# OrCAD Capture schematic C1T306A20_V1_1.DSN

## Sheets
1 PwrStr-3V3-S3
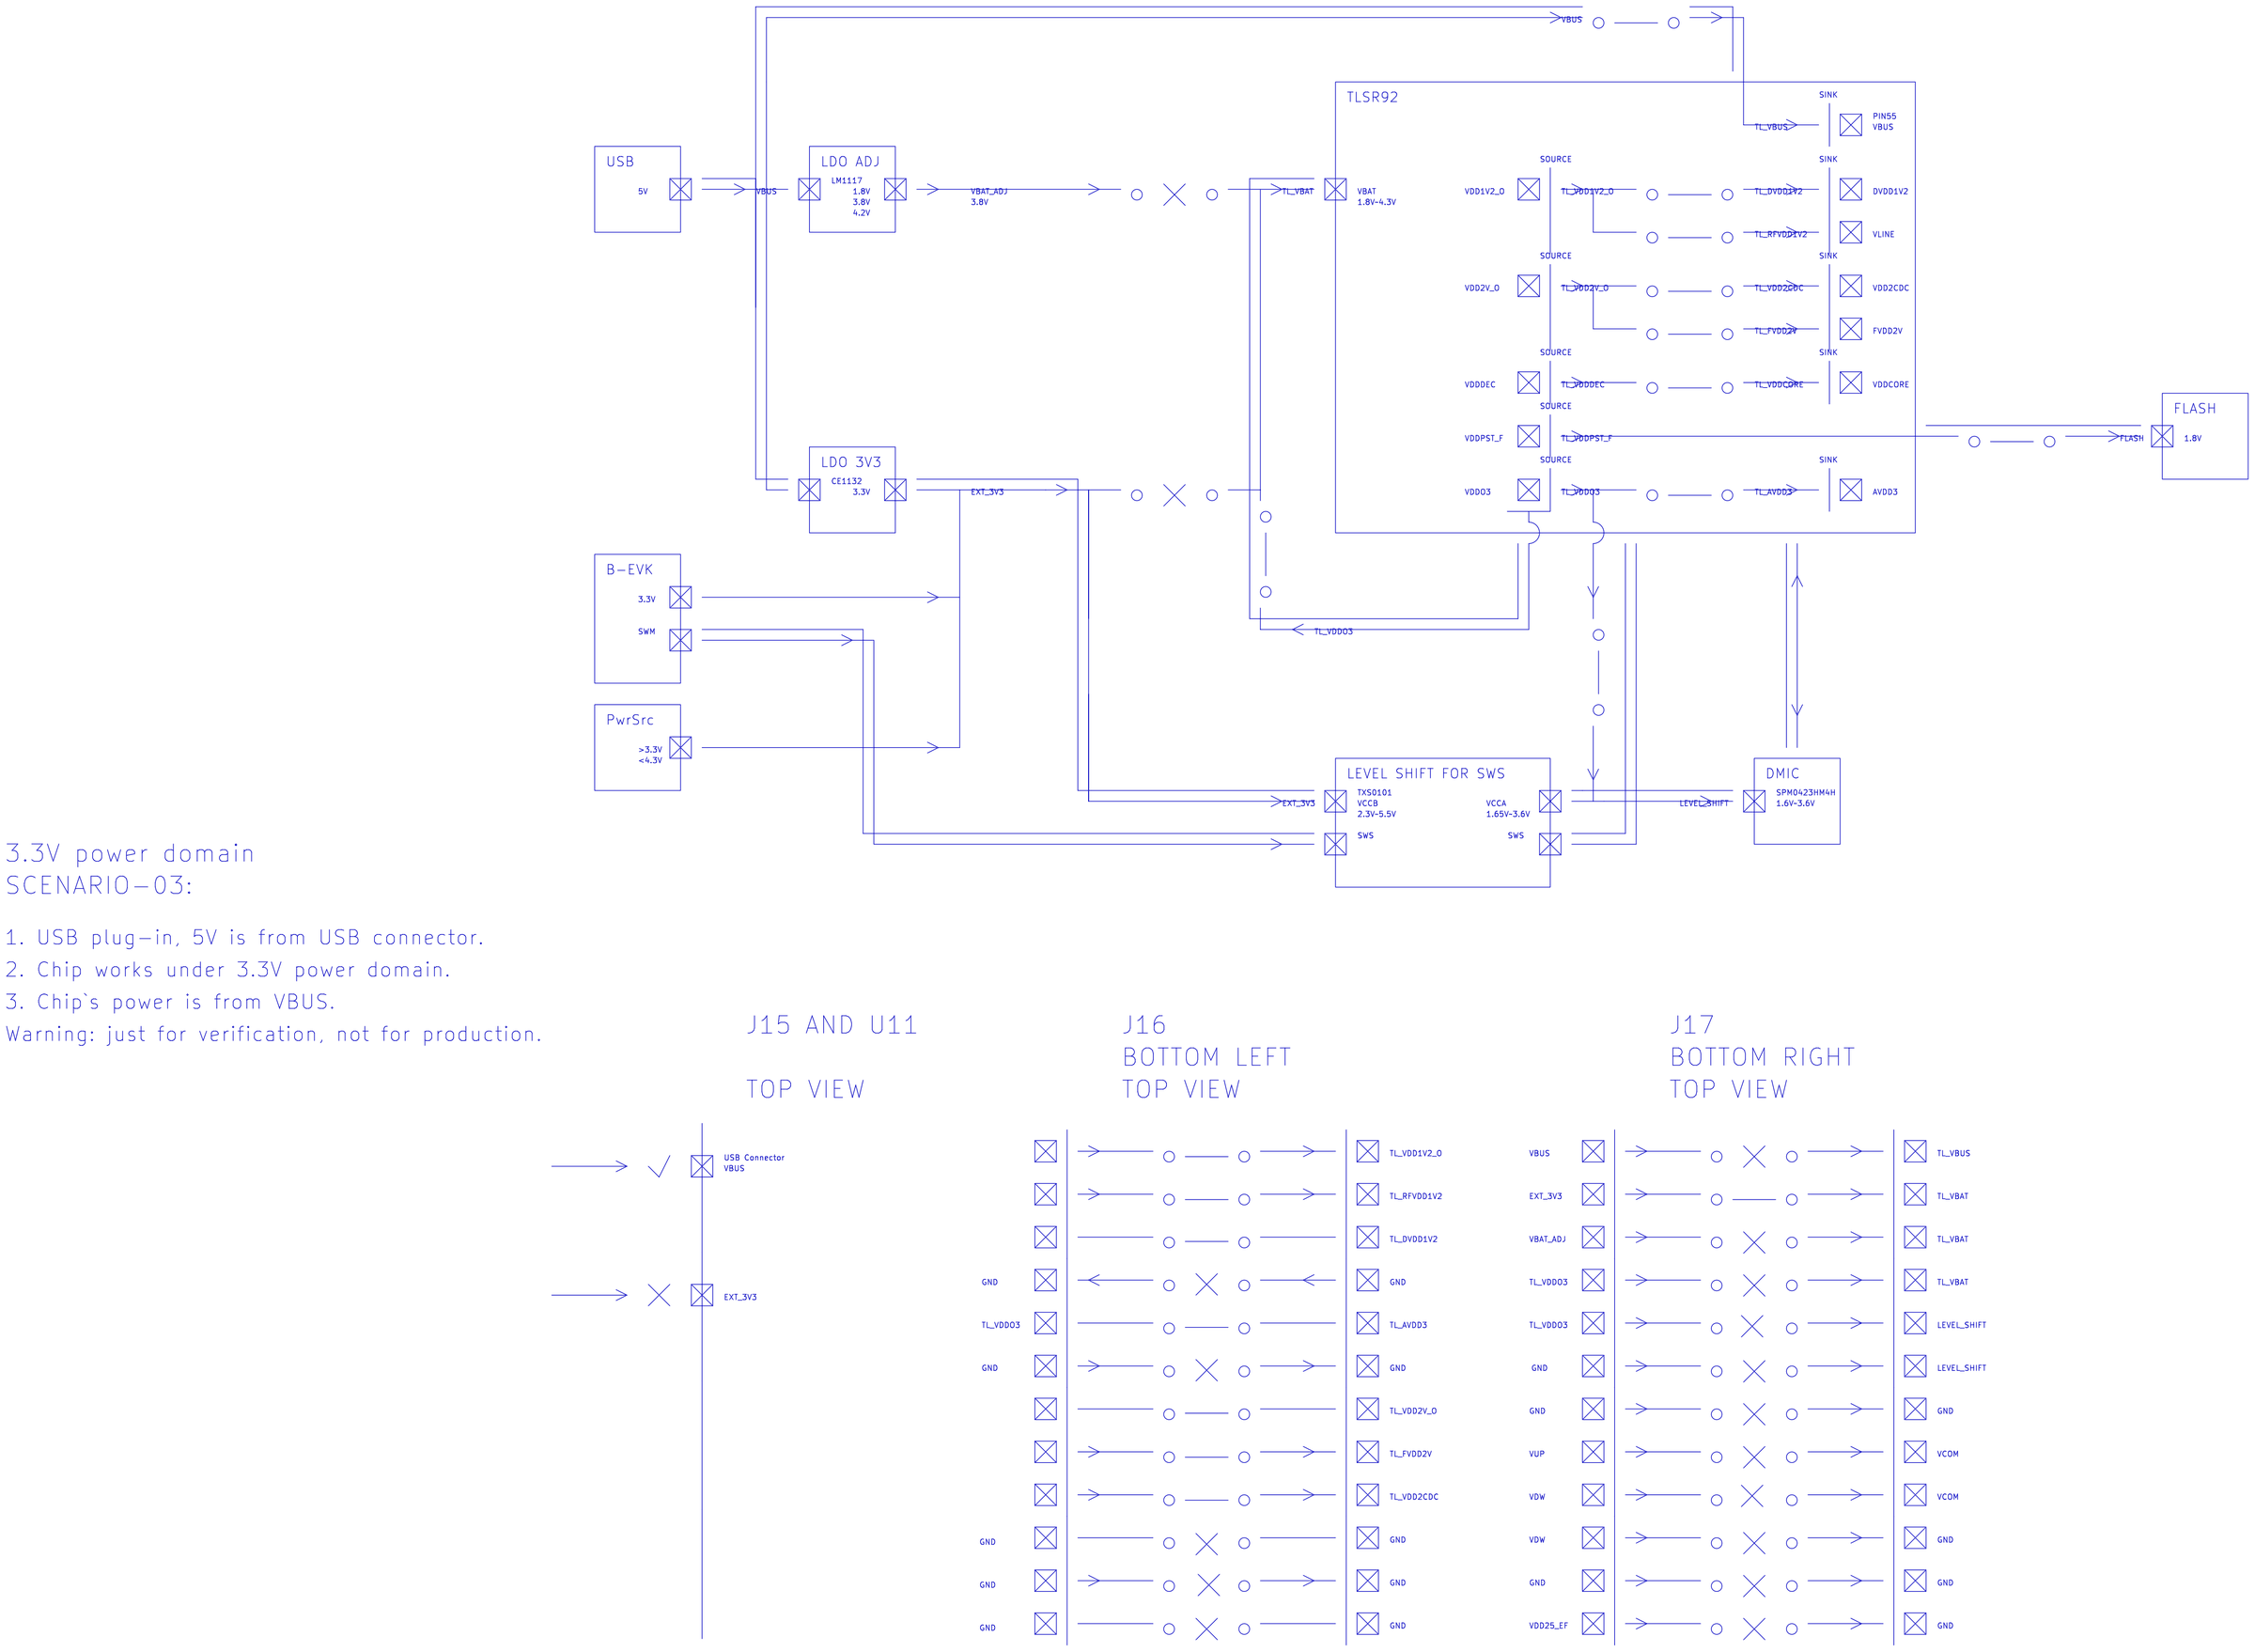
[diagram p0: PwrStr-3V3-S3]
2 PwrStr-3V3-S2
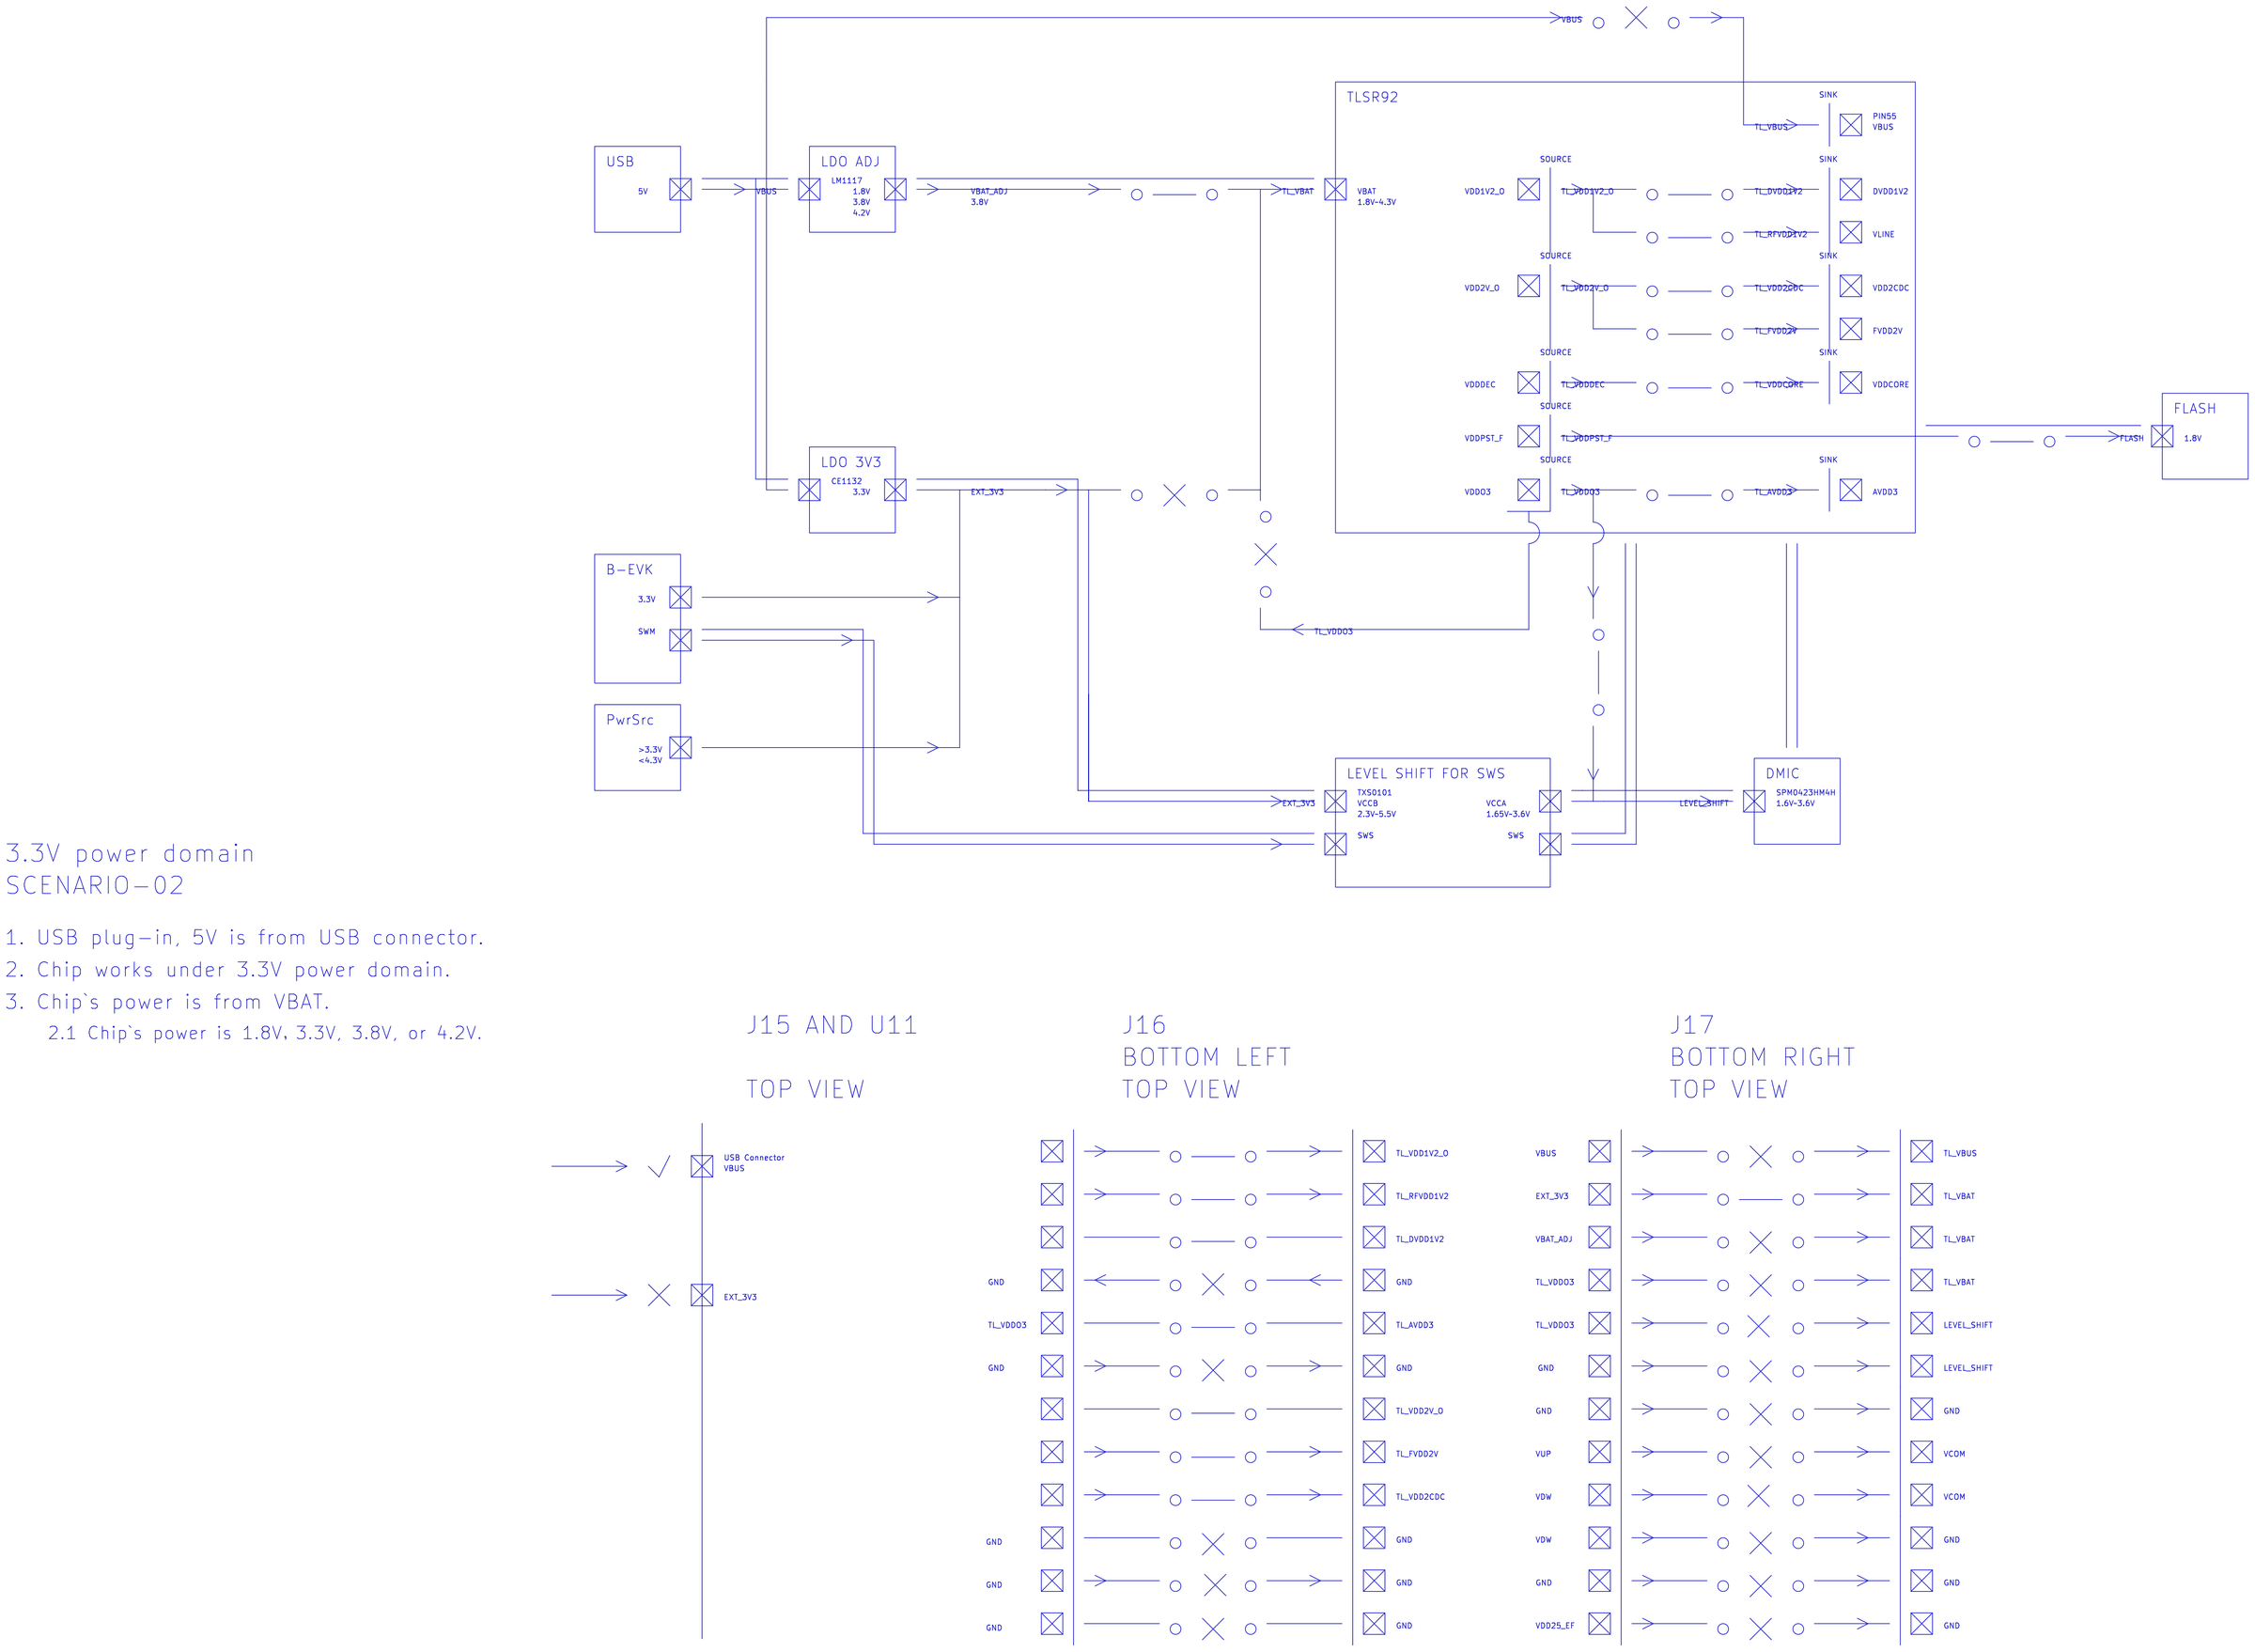
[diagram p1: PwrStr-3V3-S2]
3 PwrStr-3V3-S1
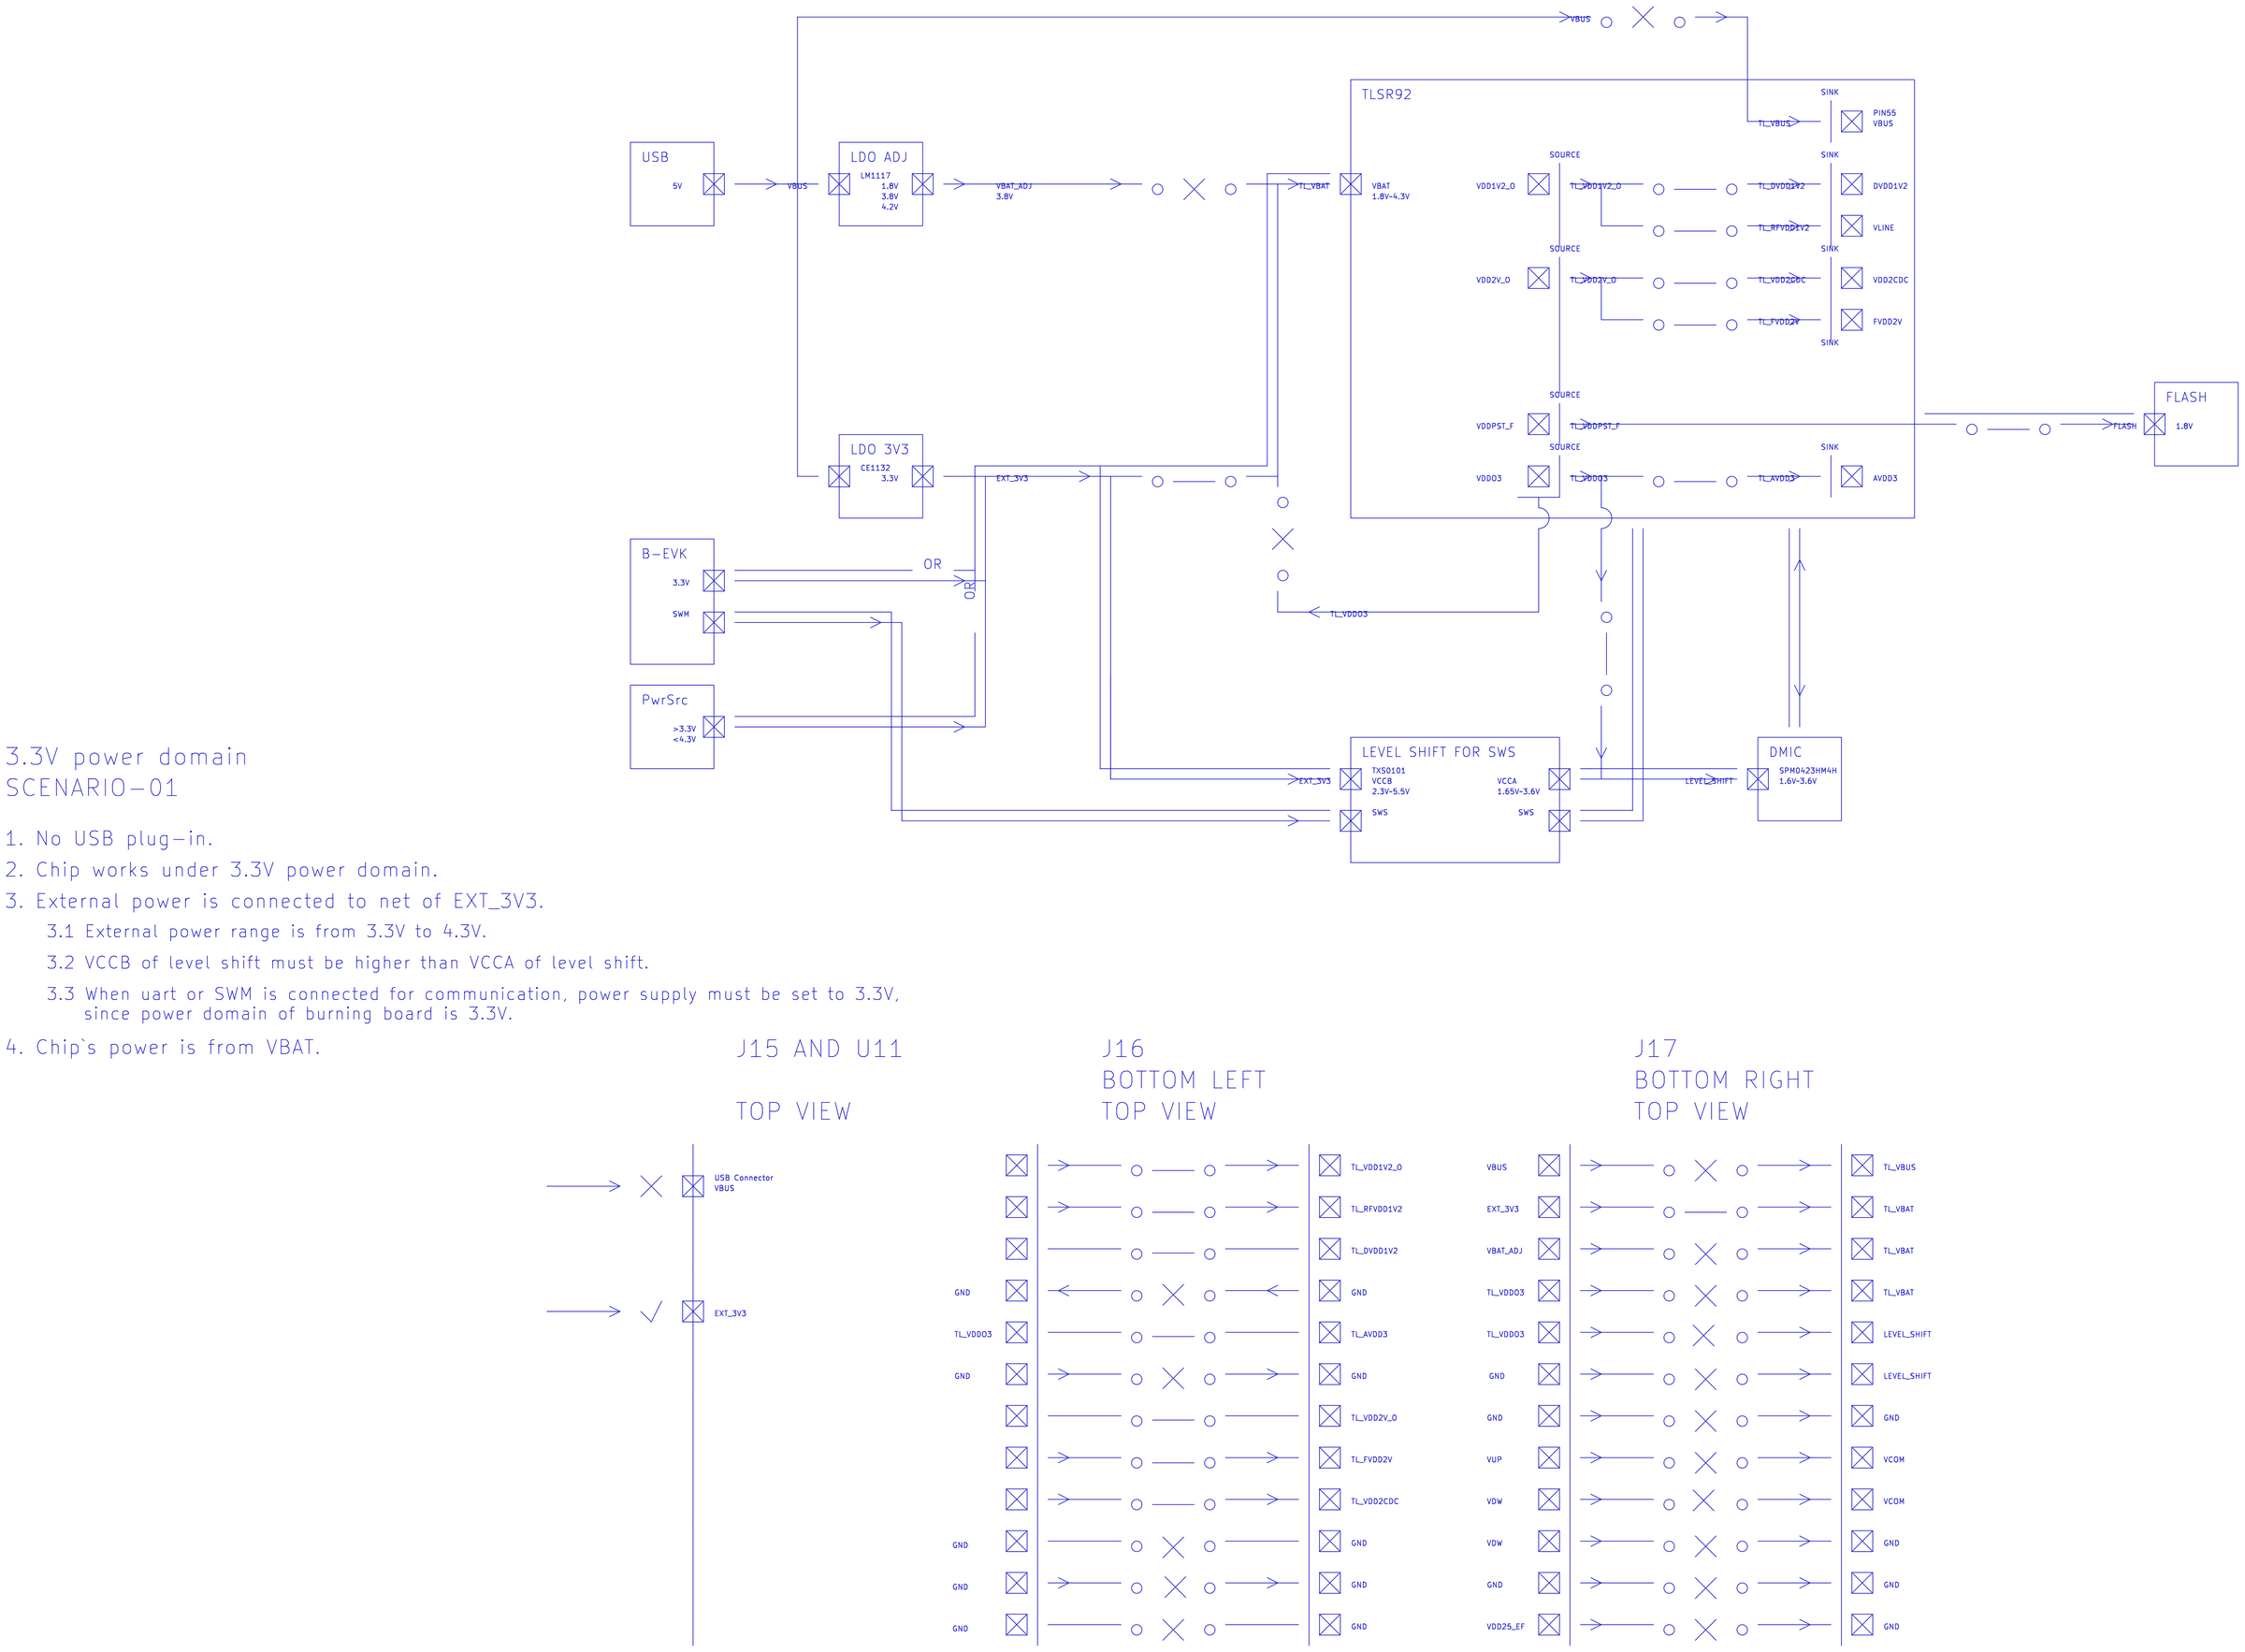
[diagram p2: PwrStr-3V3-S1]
4 000_Log: title: TELINK; rev: V1.0; note: C1T306A20
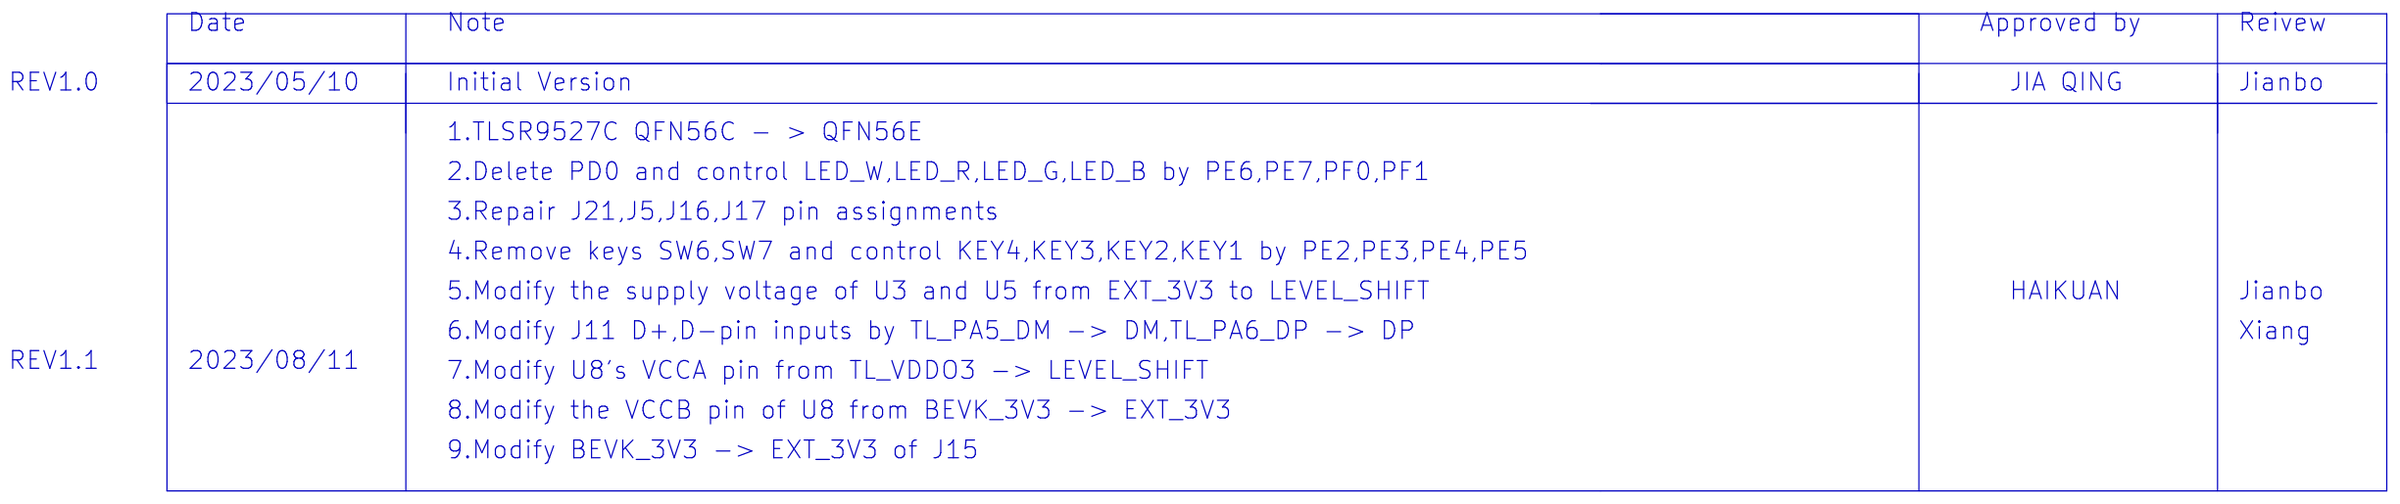
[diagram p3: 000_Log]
5 001_Structure: title: TELINK; rev: V1.1; note: C1T306A20
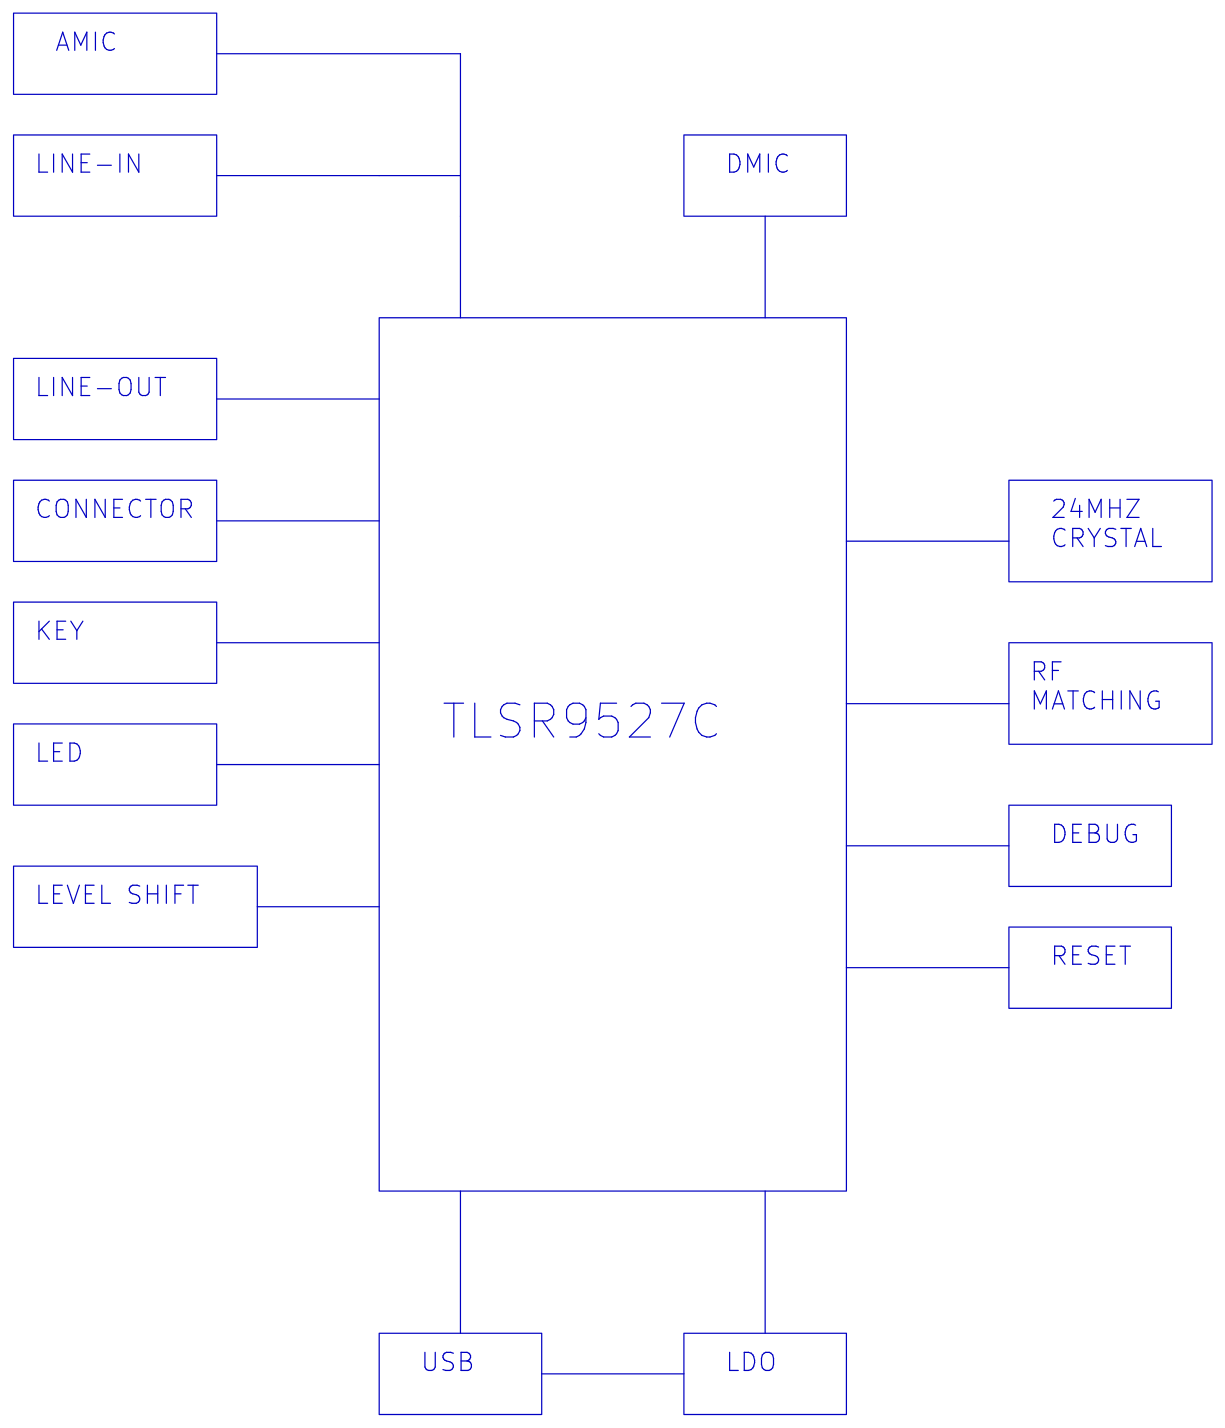
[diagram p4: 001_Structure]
6 003_MCU: size A3; title: TELINK; rev: V1.1; note: C1T306A20
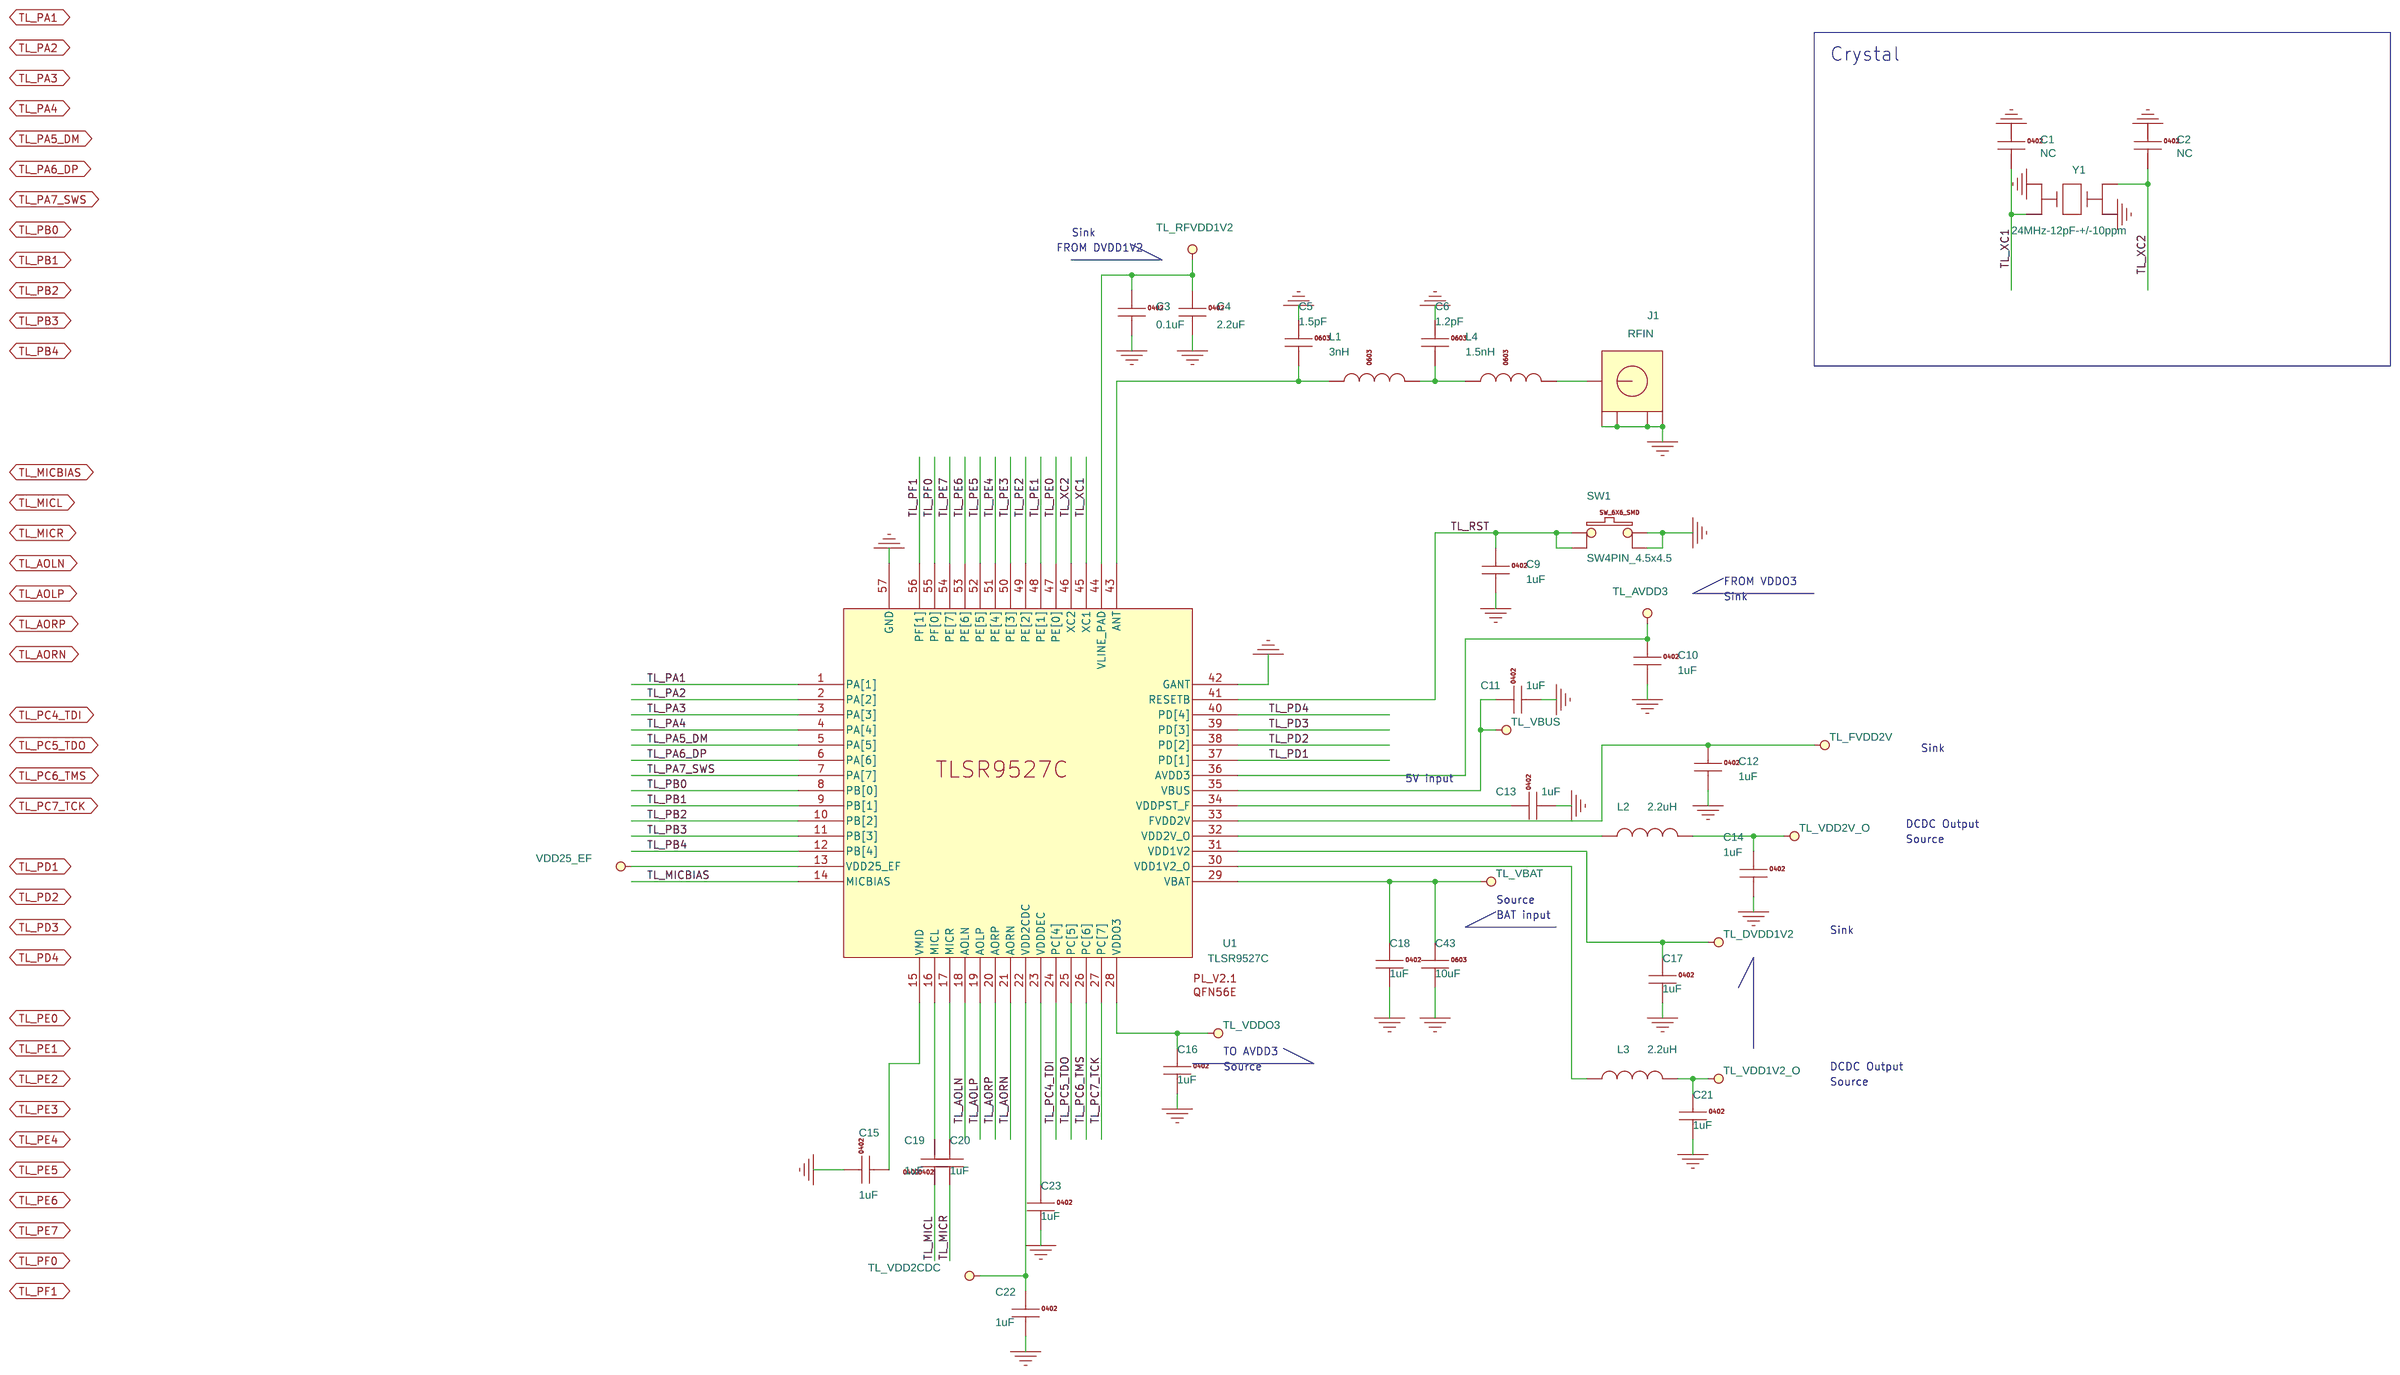
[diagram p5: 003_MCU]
7 004_INTERFACE: size A3; title: TELINK; rev: V1.1; note: C1T306A20
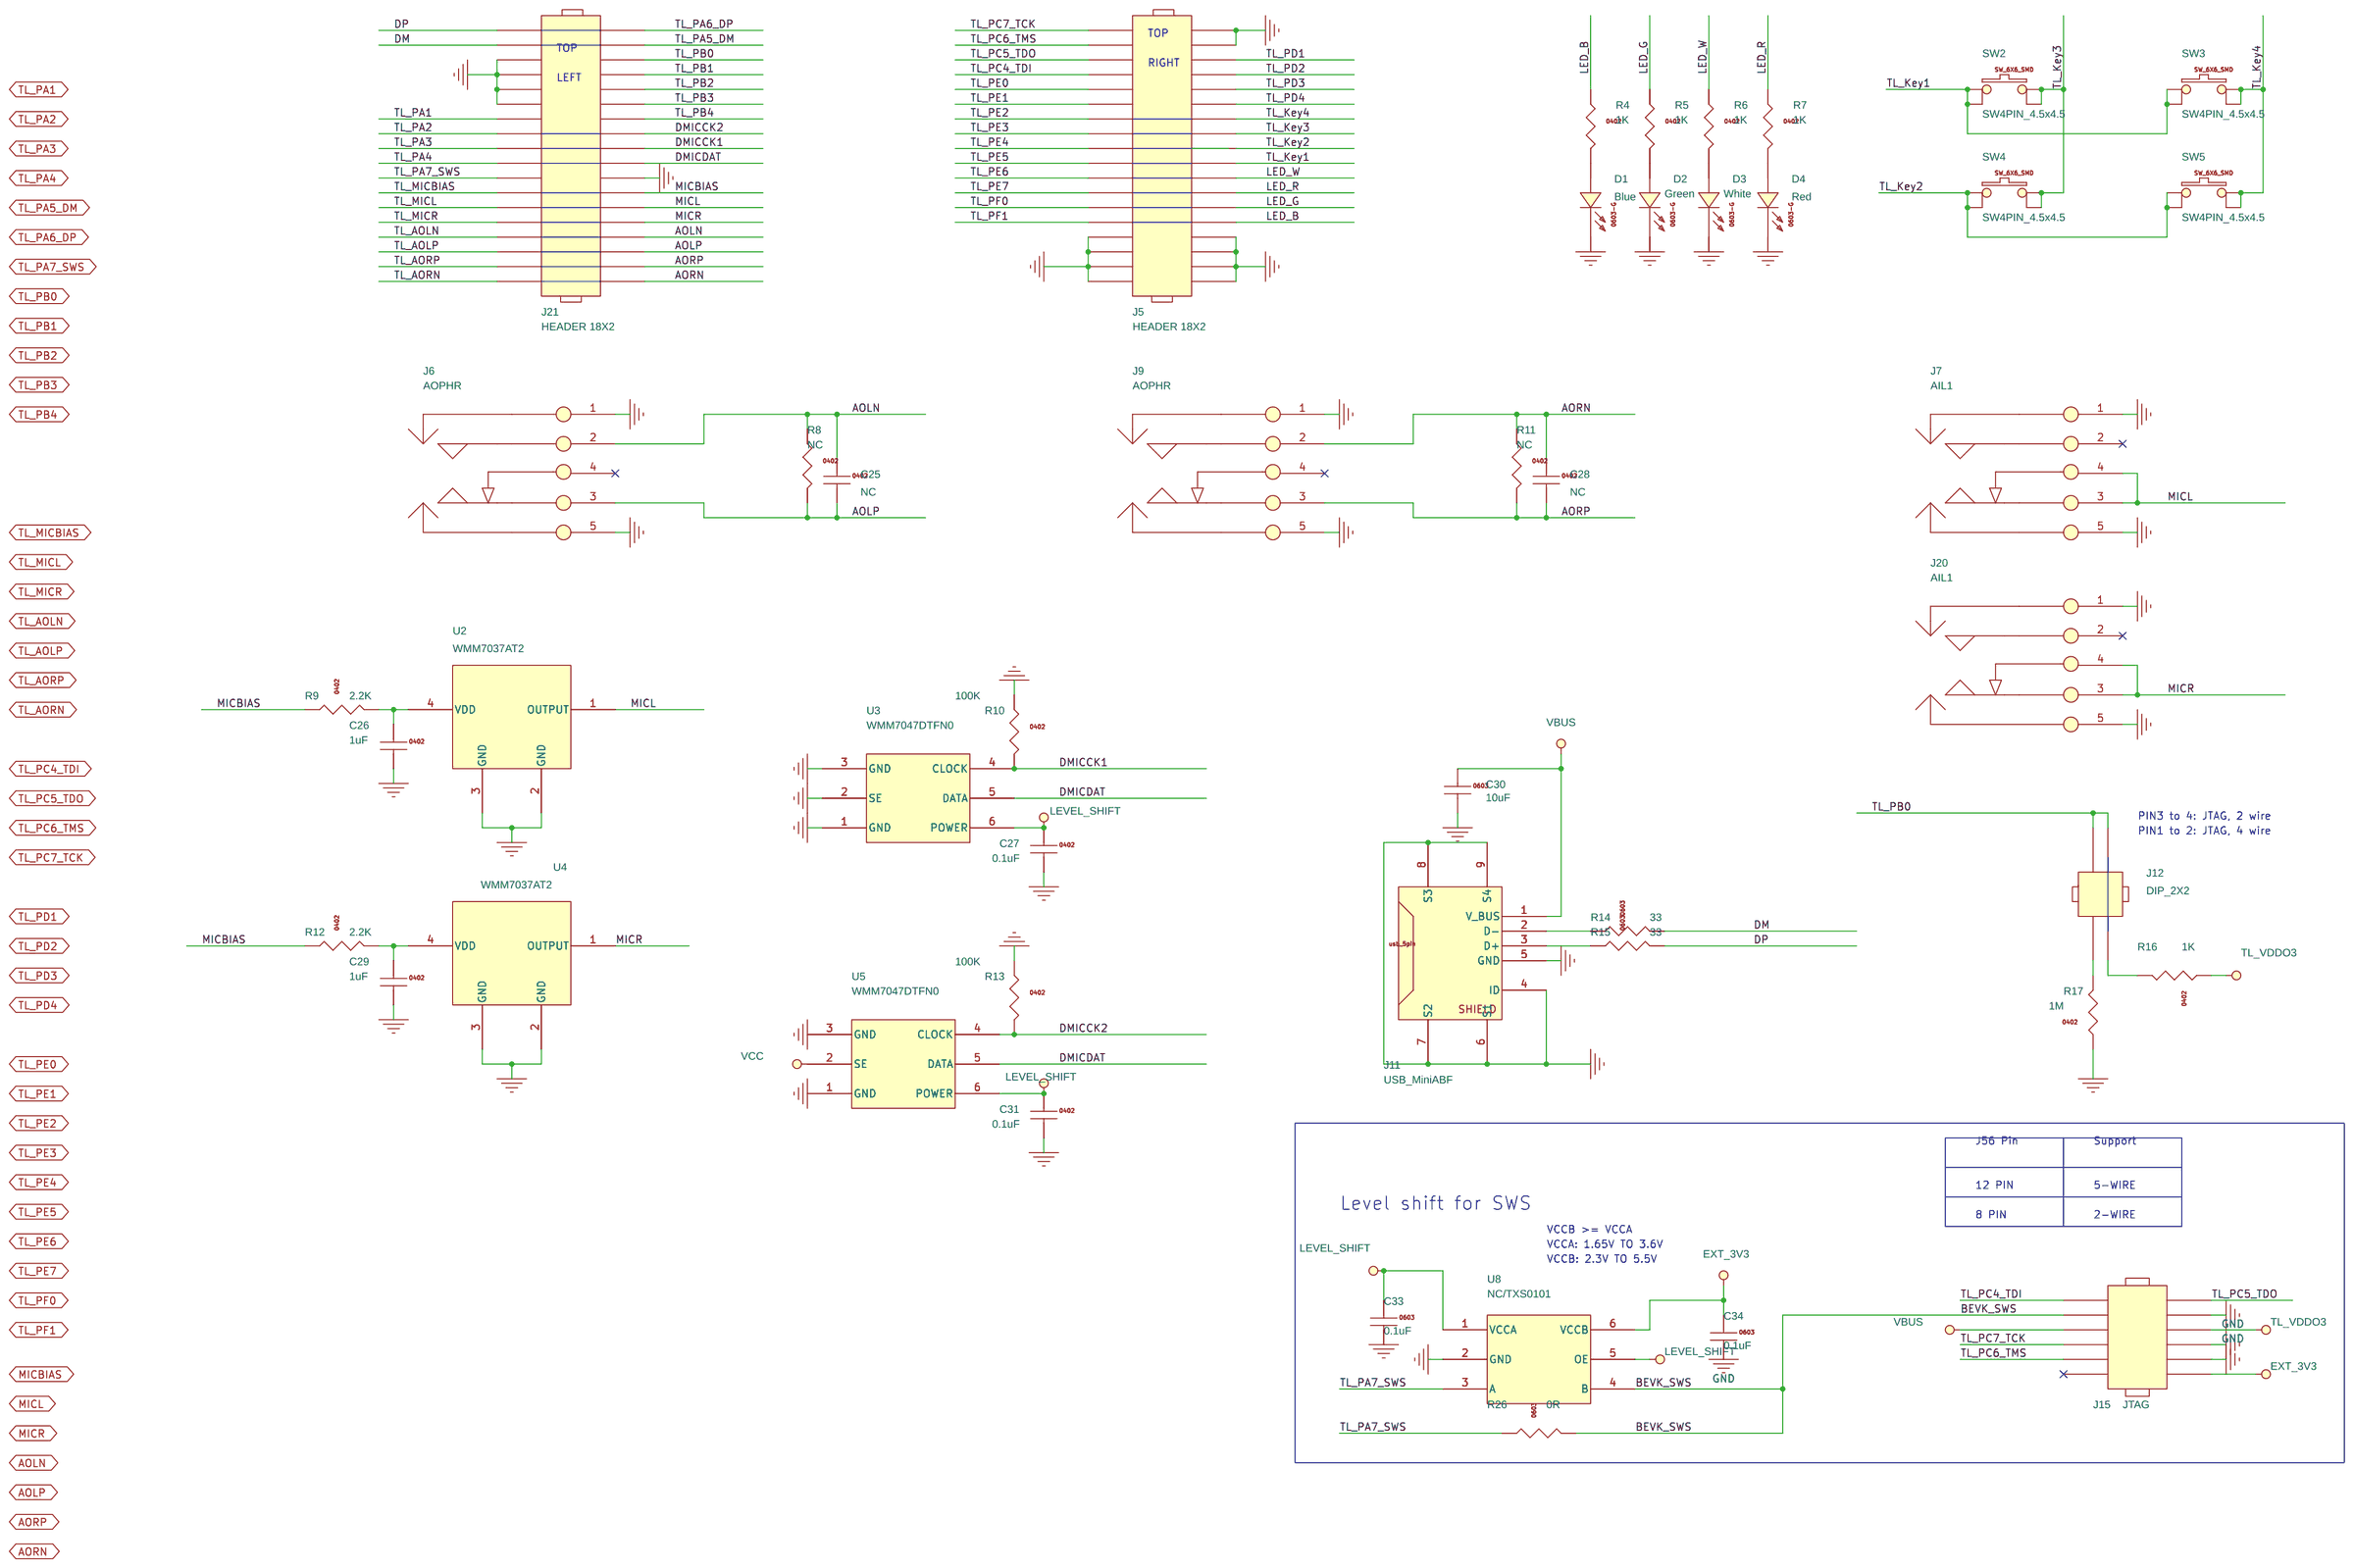
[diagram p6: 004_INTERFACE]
8 005_POWER: size A3; title: TELINK; rev: V1.1; note: C1T306A20
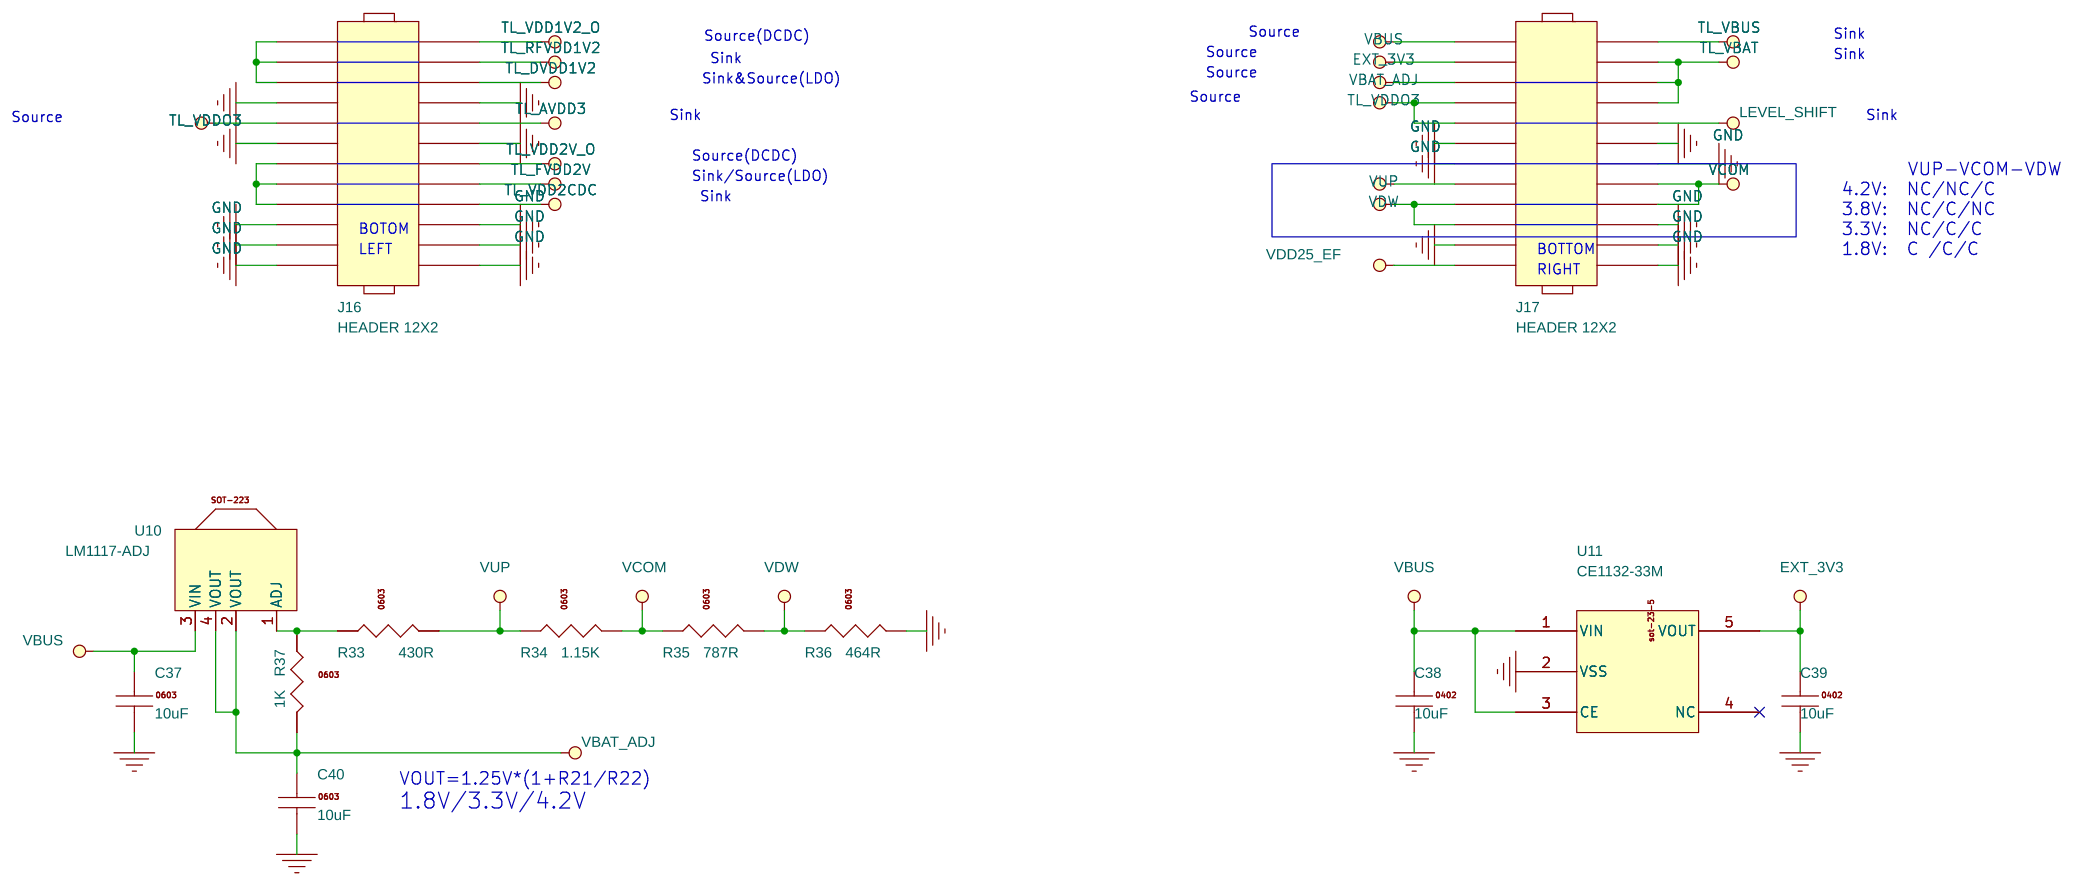
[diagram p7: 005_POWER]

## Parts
sheet 003_MCU
C1  NC  [0402]
C2  NC  [0402]
C3  0.1uF  [0402]
C4  2.2uF  [0402]
C5  1.5pF  [0402]
C6  1.2pF  [0402]
C9  1uF  [0402]
C10  1uF  [0402]
C11  1uF  [0402]
C12  1uF  [0402]
C13  1uF  [0402]
C14  1uF  [0402]
C15  1uF  [0402]
C16  1uF  [0402]
C17  1uF  [0402]
C18  1uF  [0402]
C19  1uF  [0402]
C20  1uF  [0402]
C21  1uF  [0402]
C22  1uF  [0402]
C23  1uF  [0402]
C43  10uF  [0603C]
J1  RFIN  [SMA-H]
L1  3nH  [0402]
L2  2.2uH  [0805L]
L3  2.2uH  [0805L]
L4  1.5nH  [0402]
SW1  SW4PIN_4.5x4.5  [SW_6X6_SMD]
U1  TLSR9527C  [qfn_7x7_56pin_0p4_5p20x5p20]
Y1  24MHz-12pF-+/-10ppm  [OSCCC250X320X110]
sheet 004_INTERFACE
C25  NC  [0402]
C26  1uF  [0402]
C27  0.1uF  [0402]
C28  NC  [0402]
C29  1uF  [0402]
C30  10uF  [0603C]
C31  0.1uF  [0402]
C33  0.1uF  [0402]
C34  0.1uF  [0402]
D1  Blue  [0603-LED]
D2  Green  [0603-LED]
D3  White  [0603-LED]
D4  Red  [0603-LED]
J5  HEADER 18X2  [smd254m-2x18_rx1_30y2_40]
J6  AOPHR  [PJ-327]
J7  AIL1  [PJ-327]
J9  AOPHR  [PJ-327]
J11  USB_MiniABF  [USB-MINI-F5]
J12  DIP_2X2  [DipSwitch_2p54_7p62_2x2]
J15  JTAG  [hdr254f-2x6x850]
J20  AIL1  [PJ-327]
J21  HEADER 18X2  [smd254m-2x18_rx1_30y2_40]
R4  1K  [0402]
R5  1K  [0402]
R6  1K  [0402]
R7  1K  [0402]
R8  NC  [0402]
R9  2.2K  [0402]
R10  100K  [0402]
R11  NC  [0402]
R12  2.2K  [0402]
R13  100K  [0402]
R14  33  [0402R]
R15  33  [0402R]
R16  1K  [0402]
R17  1M  [0402]
R26  0R  [0402R]
SW2  SW4PIN_4.5x4.5  [SW_6X6_SMD]
SW3  SW4PIN_4.5x4.5  [SW_6X6_SMD]
SW4  SW4PIN_4.5x4.5  [SW_6X6_SMD]
SW5  SW4PIN_4.5x4.5  [SW_6X6_SMD]
U2  WMM7037AT2  [ga_bfa423_a83]
U3  WMM7047DTFN0  [DMIC_SPM0423HM4H-WB]
U4  WMM7037AT2  [ga_bfa423_a83]
U5  WMM7047DTFN0  [DMIC_SPM0423HM4H-WB]
U8  NC/TXS0101  [sc70-6]
sheet 005_POWER
C37  10uF  [0603c]
C38  10uF  [0603C]
C39  10uF  [0603C]
C40  10uF  [0603C]
J16  HEADER 12X2  [smd254m-2x12_rx1_30y2_40]
J17  HEADER 12X2  [smd254m-2x12_rx1_30y2_40]
R33  430R  [0402]
R34  1.15K  [0402]
R35  787R  [0402]
R36  464R  [0402]
R37  1K  [0402]
U10  LM1117-ADJ  [sot-223]
U11  CE1132-33M  [sot-23-5]

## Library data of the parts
C1 C2 = C1005_NC
C3 C4 C9-C18 C21-C23 C26 C27 C29 C31 C38 C39 = C1005X5R1C104K
C5 C6 = C1608_NC
C19 C20 C25 C28 = C1005X5R1C105K
C43 = C1005X5R1C104K_0
J1 = SMA_JACK_2: PART: RF
L1 L4 = MLK1608_000R
L2 L3 = IND
SW1-SW5 = SW_6X6_SMD_0
U1 = TLSR9527C
Y1 = CRYSTAL4_SM_0
C30 C37 = C1608X5R0J106M
C33 C34 C40 = C1608X5R1C105M
D1-D4 = 0603D_Green
J5 J21 = HEADER_18X2
J6 J7 J9 J20 = PJ327_2_v2
J11 = USB_MiniABF_5pin
J12 = HEADER_2X2_0
J15 = HEADER_6X2
R4-R7 = RS0402K102JT
R8-R13 R16 R17 = RS0402K104JT
R14 R15 = RS0603K330JT
R26 = RS0603K102JT
U2 U4 = MULPS4CX-RM5_0
U3 U5 = LD1117_SO_0
U8 = TXS0101
J16 J17 = HEADER_12X2
R33-R37 = RS0603K104JT
U10 = XC62FP3302_0.3V_SOT-89
U11 = XC6219_6.3V_SOT-23-5

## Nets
GND: C1.1 C2.1 C3.2 C4.2 C5.1 C6.1 C9.2 C10.2 C11.2 C12.2 C13.2 C14.2 C15.1 C16.2 C17.2 C18.2 C21.2 C22.2 C23.2 C26.2 C27.2 C29.2 C30.2 C31.2 C33.2 C34.2 C37.2 C38.2 C39.2 C40.2 C43.2 D1.C(CATHODE) D2.C(CATHODE) D3.C(CATHODE) D4.C(CATHODE) J1.2 J1.3 J1.4 J1.5 J5.1 J5.3 J5.29 J5.30 J5.31 J5.32 J5.33 J5.34 J5.35 J5.36 J6.1 J6.5 J7.1 J7.5 J9.1 J9.5 J11.4(ID) J11.5(GND) J11.6(S1) J11.7(S2) J11.8(S3) J11.9(S4) J15.3 J15.5 J15.9 J16.7 J16.8 J16.11 J16.12 J16.19 J16.20 J16.21 J16.22 J16.23 J16.24 J17.11 J17.12 J17.13 J17.14 J17.19 J17.21 J17.22 J17.23 J20.1 J20.5 J21.6 J21.8 J21.10 J21.12 J21.21 R10.1 R13.1 R17.1 R36.2 SW1.3 SW1.4 U1.42(GANT) U1.57(GND) U2.2(GND) U2.3(GND) U3.1(GND) U3.2(SE) U3.3(GND) U4.2(GND) U4.3(GND) U5.1(GND) U5.3(GND) U8.2(GND) U11.2(VSS) Y1.2 Y1.4
VBAT_ADJ: C40.1 J17.6 R37.2 U10.2(VOUT) U10.4(VOUT)
VBUS: C30.1 C37.1 C38.1 J11.1(V_BUS) J15.8 J17.2 U10.3(VIN) U11.1(VIN) U11.3(CE)
VDD25_EF: J17.24 U1.13(VDD25_EF)
AOLN: C25.1 J6.2 J21.29 R8.1
AOLP: C25.2 J6.3 J21.31 R8.2
AORN: C28.1 J9.2 J21.35 R11.1
AORP: C28.2 J9.3 J21.33 R11.2
BEVK_SWS: J15.10 R26.2 U8.4(B)
DM: J21.4 R14.2
DMICCK1: J21.17 R10.2 U3.4(CLOCK)
DMICCK2: J21.15 R13.2 U5.4(CLOCK)
DMICDAT: J21.19 U3.5(DATA) U5.5(DATA)
DP: J21.2 R15.2
EXT_3V3: C34.1 C39.1 J15.1 J17.4 U8.6(VCCB) U11.5(VOUT)
LED_B: J5.27 R4.1
LED_G: J5.25 R5.1
LED_R: J5.23 R7.1
LED_W: J5.21 R6.1
LEVEL_SHIFT: C27.1 C31.1 C33.1 J17.9 U3.6(POWER) U5.2(SE) U5.6(POWER) U8.1(VCCA) U8.5(OE)
MICBIAS: J21.23 R9.1 R12.1
MICL: J7.3 J7.4 J21.25 U2.1(OUTPUT)
MICR: J20.3 J20.4 J21.27 U4.1(OUTPUT)
TL_AOLN: U1.18(AOLN)
TL_AOLN (page 004_INTERFACE): J21.30
TL_AOLP: U1.19(AOLP)
TL_AOLP (page 004_INTERFACE): J21.32
TL_AORN: U1.21(AORN)
TL_AORN (page 004_INTERFACE): J21.36
TL_AORP: U1.20(AORP)
TL_AORP (page 004_INTERFACE): J21.34
TL_AVDD3: C10.1 J16.9 U1.36(AVDD3)
TL_DVDD1V2: C17.1 J16.5 U1.31(VDD1V2)
TL_FVDD2V: C12.1 J16.15 U1.33(FVDD2V)
TL_Key1: J5.19 SW2.1 SW2.2 SW3.1 SW3.2
TL_Key2: J5.17 SW4.1 SW4.2 SW5.1 SW5.2
TL_Key3: J5.15 SW2.3 SW2.4 SW4.3 SW4.4
TL_Key4: J5.13 SW3.3 SW3.4 SW5.3 SW5.4
TL_MICBIAS: U1.14(MICBIAS)
TL_MICBIAS (page 004_INTERFACE): J21.24
TL_MICL: C19.1
TL_MICL (page 004_INTERFACE): J21.26
TL_MICR: C20.1
TL_MICR (page 004_INTERFACE): J21.28
TL_PA1: U1.1(PA[1])
TL_PA1 (page 004_INTERFACE): J21.14
TL_PA2: U1.2(PA[2])
TL_PA2 (page 004_INTERFACE): J21.16
TL_PA3: U1.3(PA[3])
TL_PA3 (page 004_INTERFACE): J21.18
TL_PA4: U1.4(PA[4])
TL_PA4 (page 004_INTERFACE): J21.20
TL_PA5_DM: U1.5(PA[5])
TL_PA5_DM (page 004_INTERFACE): J21.3
TL_PA6_DP: U1.6(PA[6])
TL_PA6_DP (page 004_INTERFACE): J21.1
TL_PA7_SWS: U1.7(PA[7])
TL_PA7_SWS (page 004_INTERFACE): J21.22 R26.1 U8.3(A)
TL_PB0: U1.8(PB[0])
TL_PB0 (page 004_INTERFACE): J12.1 J12.3 J21.5
TL_PB1: U1.9(PB[1])
TL_PB1 (page 004_INTERFACE): J21.7
TL_PB2: U1.10(PB[2])
TL_PB2 (page 004_INTERFACE): J21.9
TL_PB3: U1.11(PB[3])
TL_PB3 (page 004_INTERFACE): J21.11
TL_PB4: U1.12(PB[4])
TL_PB4 (page 004_INTERFACE): J21.13
TL_PC4_TDI: U1.24(PC[4])
TL_PC4_TDI (page 004_INTERFACE): J5.8 J15.12
TL_PC5_TDO: U1.25(PC[5])
TL_PC5_TDO (page 004_INTERFACE): J5.6 J15.11
TL_PC6_TMS: U1.26(PC[6])
TL_PC6_TMS (page 004_INTERFACE): J5.4 J15.4
TL_PC7_TCK: U1.27(PC[7])
TL_PC7_TCK (page 004_INTERFACE): J5.2 J15.6
TL_PD1: U1.37(PD[1])
TL_PD1 (page 004_INTERFACE): J5.5
TL_PD2: U1.38(PD[2])
TL_PD2 (page 004_INTERFACE): J5.7
TL_PD3: U1.39(PD[3])
TL_PD3 (page 004_INTERFACE): J5.9
TL_PD4: U1.40(PD[4])
TL_PD4 (page 004_INTERFACE): J5.11
TL_PE0: U1.47(PE[0])
TL_PE0 (page 004_INTERFACE): J5.10
TL_PE1: U1.48(PE[1])
TL_PE1 (page 004_INTERFACE): J5.12
TL_PE2: U1.49(PE[2])
TL_PE2 (page 004_INTERFACE): J5.14
TL_PE3: U1.50(PE[3])
TL_PE3 (page 004_INTERFACE): J5.16
TL_PE4: U1.51(PE[4])
TL_PE4 (page 004_INTERFACE): J5.18
TL_PE5: U1.52(PE[5])
TL_PE5 (page 004_INTERFACE): J5.20
TL_PE6: U1.53(PE[6])
TL_PE6 (page 004_INTERFACE): J5.22
TL_PE7: U1.54(PE[7])
TL_PE7 (page 004_INTERFACE): J5.24
TL_PF0: U1.55(PF[0])
TL_PF0 (page 004_INTERFACE): J5.26
TL_PF1: U1.56(PF[1])
TL_PF1 (page 004_INTERFACE): J5.28
TL_RFVDD1V2: C3.1 C4.1 J16.3 U1.44(VLINE_PAD)
TL_RST: C9.1 SW1.1 SW1.2 U1.41(RESETB)
TL_VBAT: C18.1 C43.1 J17.3 J17.5 J17.7 U1.29(VBAT)
TL_VBUS: C11.1 J17.1 U1.35(VBUS)
TL_VDD1V2_O: C21.1 J16.1 L3.2
TL_VDD2CDC: C22.1 J16.17 U1.22(VDD2CDC)
TL_VDD2V_O: C14.1 J16.13 L2.2
TL_VDDO3: C16.1 J15.7 J16.10 J17.8 J17.10 R16.1 U1.28(VDDO3)
TL_XC1: C1.2 U1.45(XC1) Y1.3
TL_XC2: C2.2 U1.46(XC2) Y1.1
VCOM: J17.15 J17.17 R34.2 R35.1
VDW: J17.18 J17.20 R35.2 R36.1
VUP: J17.16 R33.2 R34.1
N20028206: R33.1 R37.1 U10.1(ADJ)
N20031302: L3.1 U1.30(VDD1V2_O)
N20031350: L2.1 U1.32(VDD2V_O)
N20031395: C13.1 U1.34(VDDPST_F)
N20031514: C5.2 L1.1 U1.43(ANT)
N20031520: C6.2 L1.2 L4.1
N20031898: C23.1 U1.23(VDDDEC)
N20035363: C26.1 R9.2 U2.4(VDD)
N20035591: C29.1 R12.2 U4.4(VDD)
N20050417: J11.3(D+) R15.1
N20050429: J11.2(D-) R14.1
N20115519: J1.1 L4.2
N20131372: C15.2 U1.15(VMID)
N20131385: C20.2 U1.17(MICR)
N20131404: C19.2 U1.16(MICL)
N20132075: D4.A(ANODE) R7.2
N20132082: D3.A(ANODE) R6.2
N20132087: D1.A(ANODE) R4.2
N20132090: D2.A(ANODE) R5.2
N20142968: J12.2 R17.2
N20142970: J12.4 R16.2
N20184397: J16.2 J16.4 J16.6
N20184465: J16.14 J16.16 J16.18

Not connected (* = marked no-connect by the designer): J6 4*; J7 2*; J9 4*; J15 2*; J20 2*; U11 4(NC)*

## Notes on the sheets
sheet 1
- VBUS
- TLSR92
- SINK
- TL_VBUS
- PIN55
- VBUS
- USB
- LDO ADJ
- SOURCE
- SINK
- 5V
- VBUS
- LM1117
- 1.8V
- VBAT_ADJ
- TL_VBAT
- VBAT
- VDD1V2_O
- TL_VDD1V2_O
- TL_DVDD1V2
- DVDD1V2
- 3.8V
- 3.8V
- 1.8V~4.3V
- 4.2V
- TL_RFVDD1V2
- VLINE
- SOURCE
- SINK
- VDD2V_O
- TL_VDD2V_O
- TL_VDD2CDC
- VDD2CDC
- TL_FVDD2V
- FVDD2V
- SOURCE
- SINK
- VDDDEC
- TL_VDDDEC
- TL_VDDCORE
- VDDCORE
- SOURCE
- FLASH
- VDDPST_F
- TL_VDDPST_F
- FLASH
- 1.8V
- LDO 3V3
- SOURCE
- SINK
- CE1132
- 3.3V
- EXT_3V3
- VDDO3
- TL_VDDO3
- TL_AVDD3
- AVDD3
- B-EVK
- 3.3V
- SWM
- TL_VDDO3
- PwrSrc
- <4.3V
- >3.3V
- LEVEL SHIFT FOR SWS
- DMIC
- TXS0101
- SPM0423HM4H
- EXT_3V3
- VCCB
- VCCA
- LEVEL_SHIFT
- 1.6V~3.6V
- 2.3V~5.5V
- 1.65V~3.6V
- SWS
- SWS
- 3.3V power domain
- SCENARIO-03:
- 1. USB plug-in, 5V is from USB connector.
- 2. Chip works under 3.3V power domain.
- 3. Chip`s power is from VBUS.
- J15 AND U11
- J16
- J17
- Warning: just for verification, not for production.
- BOTTOM LEFT
- BOTTOM RIGHT
- TOP VIEW
- TOP VIEW
- TOP VIEW
- TL_VDD1V2_O
- VBUS
- TL_VBUS
- USB Connector
- VBUS
- TL_RFVDD1V2
- EXT_3V3
- TL_VBAT
- TL_DVDD1V2
- VBAT_ADJ
- TL_VBAT
- GND
- GND
- TL_VDDO3
- TL_VBAT
- EXT_3V3
- TL_VDDO3
- TL_AVDD3
- TL_VDDO3
- LEVEL_SHIFT
- GND
- GND
- GND
- LEVEL_SHIFT
- TL_VDD2V_O
- GND
- GND
- TL_FVDD2V
- VUP
- VCOM
- TL_VDD2CDC
- VDW
- VCOM
- GND
- GND
- VDW
- GND
- GND
- GND
- GND
- GND
- GND
- GND
- VDD25_EF
- GND
sheet 2
- VBUS
- TLSR92
- SINK
- TL_VBUS
- PIN55
- VBUS
- USB
- LDO ADJ
- SOURCE
- SINK
- 5V
- VBUS
- LM1117
- 1.8V
- VBAT_ADJ
- TL_VBAT
- VBAT
- VDD1V2_O
- TL_VDD1V2_O
- TL_DVDD1V2
- DVDD1V2
- 3.8V
- 3.8V
- 1.8V~4.3V
- 4.2V
- TL_RFVDD1V2
- VLINE
- SOURCE
- SINK
- VDD2V_O
- TL_VDD2V_O
- TL_VDD2CDC
- VDD2CDC
- TL_FVDD2V
- FVDD2V
- SOURCE
- SINK
- VDDDEC
- TL_VDDDEC
- TL_VDDCORE
- VDDCORE
- SOURCE
- FLASH
- VDDPST_F
- TL_VDDPST_F
- FLASH
- 1.8V
- LDO 3V3
- SOURCE
- SINK
- CE1132
- 3.3V
- EXT_3V3
- VDDO3
- TL_VDDO3
- TL_AVDD3
- AVDD3
- B-EVK
- 3.3V
- SWM
- TL_VDDO3
- PwrSrc
- <4.3V
- >3.3V
- LEVEL SHIFT FOR SWS
- DMIC
- TXS0101
- SPM0423HM4H
- EXT_3V3
- VCCB
- VCCA
- LEVEL_SHIFT
- 1.6V~3.6V
- 2.3V~5.5V
- 1.65V~3.6V
- SWS
- SWS
- 3.3V power domain
- SCENARIO-02
- 1. USB plug-in, 5V is from USB connector.
- 2. Chip works under 3.3V power domain.
- 3. Chip`s power is from VBAT.
- J15 AND U11
- J16
- J17
- 2.1 Chip`s power is 1.8V，3.3V, 3.8V, or 4.2V.
- BOTTOM LEFT
- BOTTOM RIGHT
- TOP VIEW
- TOP VIEW
- TOP VIEW
- TL_VDD1V2_O
- VBUS
- TL_VBUS
- USB Connector
- VBUS
- TL_RFVDD1V2
- EXT_3V3
- TL_VBAT
- TL_DVDD1V2
- VBAT_ADJ
- TL_VBAT
- GND
- GND
- TL_VDDO3
- TL_VBAT
- EXT_3V3
- TL_VDDO3
- TL_AVDD3
- TL_VDDO3
- LEVEL_SHIFT
- GND
- GND
- GND
- LEVEL_SHIFT
- TL_VDD2V_O
- GND
- GND
- TL_FVDD2V
- VUP
- VCOM
- TL_VDD2CDC
- VDW
- VCOM
- GND
- GND
- VDW
- GND
- GND
- GND
- GND
- GND
- GND
- GND
- VDD25_EF
- GND
sheet 3
- VBUS
- TLSR92
- SINK
- TL_VBUS
- PIN55
- VBUS
- USB
- LDO ADJ
- SOURCE
- SINK
- 5V
- VBUS
- LM1117
- 1.8V
- VBAT_ADJ
- TL_VBAT
- VBAT
- VDD1V2_O
- TL_VDD1V2_O
- TL_DVDD1V2
- DVDD1V2
- 3.8V
- 3.8V
- 1.8V~4.3V
- 4.2V
- TL_RFVDD1V2
- VLINE
- SOURCE
- SINK
- VDD2V_O
- TL_VDD2V_O
- TL_VDD2CDC
- VDD2CDC
- TL_FVDD2V
- FVDD2V
- SINK
- SOURCE
- FLASH
- VDDPST_F
- TL_VDDPST_F
- FLASH
- 1.8V
- LDO 3V3
- SOURCE
- SINK
- CE1132
- 3.3V
- EXT_3V3
- VDDO3
- TL_VDDO3
- TL_AVDD3
- AVDD3
- B-EVK
- OR
- 3.3V
- OR
- SWM
- TL_VDDO3
- PwrSrc
- <4.3V
- >3.3V
- 3.3V power domain
- LEVEL SHIFT FOR SWS
- DMIC
- TXS0101
- SPM0423HM4H
- SCENARIO-01
- EXT_3V3
- VCCB
- VCCA
- LEVEL_SHIFT
- 1.6V~3.6V
- 2.3V~5.5V
- 1.65V~3.6V
- SWS
- SWS
- 1. No USB plug-in.
- 2. Chip works under 3.3V power domain.
- 3. External power is connected to net of EXT_3V3.
- 3.1 External power range is from 3.3V to 4.3V.
- 3.2 VCCB of level shift must be higher than VCCA of level shift.
- 3.3 When uart or SWM is connected for communication, power supply must be set to 3.3V,
      since power domain of burning board is 3.3V.
- 4. Chip`s power is from VBAT.
- J15 AND U11
- J16
- J17
- BOTTOM LEFT
- BOTTOM RIGHT
- TOP VIEW
- TOP VIEW
- TOP VIEW
- TL_VDD1V2_O
- VBUS
- TL_VBUS
- USB Connector
- VBUS
- TL_RFVDD1V2
- EXT_3V3
- TL_VBAT
- TL_DVDD1V2
- VBAT_ADJ
- TL_VBAT
- GND
- GND
- TL_VDDO3
- TL_VBAT
- EXT_3V3
- TL_VDDO3
- TL_AVDD3
- TL_VDDO3
- LEVEL_SHIFT
- GND
- GND
- GND
- LEVEL_SHIFT
- TL_VDD2V_O
- GND
- GND
- TL_FVDD2V
- VUP
- VCOM
- TL_VDD2CDC
- VDW
- VCOM
- GND
- GND
- VDW
- GND
- GND
- GND
- GND
- GND
- GND
- GND
- VDD25_EF
- GND
sheet 4
- Date
- Note
- Approved by
- Reivew
- REV1.0
- 2023/05/10
- Initial Version
- JIA QING
- Jianbo
- 1.TLSR9527C QFN56C - > QFN56E
- 2.Delete PD0 and control LED_W,LED_R,LED_G,LED_B by PE6,PE7,PF0,PF1
- 3.Repair J21,J5,J16,J17 pin assignments
- 4.Remove keys SW6,SW7 and control KEY4,KEY3,KEY2,KEY1 by PE2,PE3,PE4,PE5
- 5.Modify the supply voltage of U3 and U5 from EXT_3V3 to LEVEL_SHIFT
- HAIKUAN
- Jianbo
- 6.Modify J11 D+,D-pin inputs by TL_PA5_DM -> DM,TL_PA6_DP -> DP
- Xiang
- REV1.1
- 2023/08/11
- 7.Modify U8's VCCA pin from TL_VDDO3 -> LEVEL_SHIFT
- 8.Modify the VCCB pin of U8 from BEVK_3V3 -> EXT_3V3
- 9.Modify BEVK_3V3 -> EXT_3V3 of J15
sheet 5
- AMIC
- LINE-IN
- DMIC
- LINE-OUT
- CONNECTOR
- 24MHZ
  CRYSTAL
- KEY
- RF
  MATCHING
- TLSR9527C
- LED
- DEBUG
- LEVEL SHIFT
- RESET
- USB
- LDO
sheet 6
- Crystal
- Sink
- FROM DVDD1V2
- FROM VDDO3
- Sink
- Sink
- 5V input
- DCDC Output
- Source
- Source
- BAT input
- Sink
- Source
- TO AVDD3
- DCDC Output
- Source
sheet 7
- TOP
- TOP
- RIGHT
- LEFT
- PIN3 to 4: JTAG, 2 wire
- PIN1 to 2: JTAG, 4 wire
- J56 Pin
- Support
- 12 PIN
- 5-WIRE
- Level shift for SWS
- 8 PIN
- 2-WIRE
- VCCB >= VCCA
- VCCA: 1.65V TO 3.6V
- VCCB: 2.3V TO 5.5V
sheet 8
- Source(DCDC)
- Source
- Sink
- Sink
- Source
- Sink
- Sink&Source(LDO)
- Source
- Source
- Source
- Sink
- Sink
- Source(DCDC)
- Sink/Source(LDO)
- VUP-VCOM-VDW
  4.2V:  NC/NC/C
  3.8V:  NC/C/NC
  3.3V:  NC/C/C
  1.8V:  C /C/C
- Sink
- BOTOM
- LEFT
- BOTTOM
- RIGHT
- VOUT=1.25V*(1+R21/R22)
- 1.8V/3.3V/4.2V
